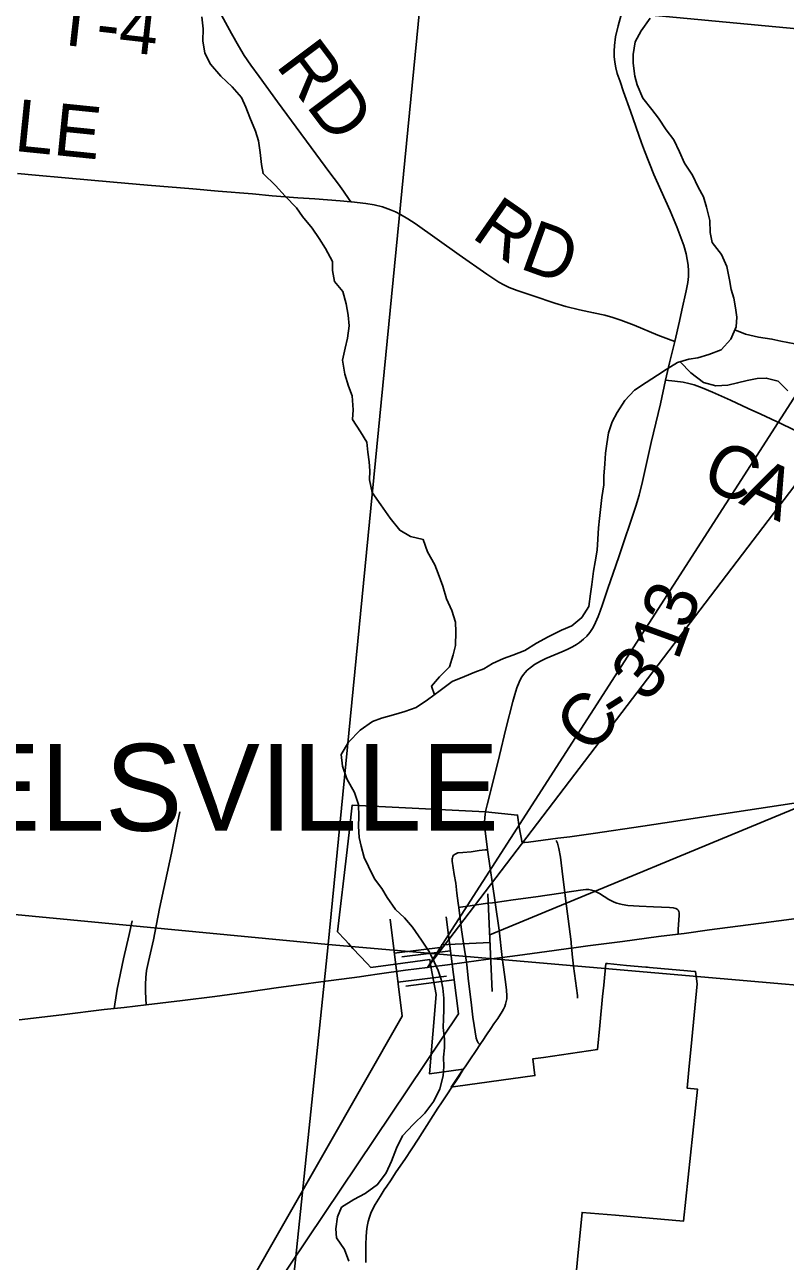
# Model space of a CAD drawing. Extents: x 0 to 1134, y 0 to 440.
# Drawn here: x 330.48 to 355.34, y 212.12 to 252.54 of the extents above; entities that cross this region are included whole.
import ezdxf

# ---------------------------------------------------------------- set-up
doc = ezdxf.new("R2010")
doc.units = 0
for name, color, linetype in [('GM_X_City_Street', 7, 'Continuous'), ('GM_X_Corporation', 7, 'Continuous'), ('GM_X_Corporation_Text', 7, 'Continuous'), ('GM_X_County_Road', 7, 'Continuous'), ('GM_X_County_Road_Text', 7, 'Continuous'), ('GM_X_Minor_River', 7, 'Continuous'), ('GM_X_Section', 7, 'Continuous'), ('GM_X_Township_Road', 7, 'Continuous'), ('GM_X_Township_Road_Text', 7, 'Continuous'), ('GM_X_US_Route', 7, 'Continuous'), ('SH_Data', 7, 'Continuous'), ('SH_Text', 7, 'Continuous'), ('SN_P_Signs', 7, 'Continuous')]:
    doc.layers.add(name, color=color, linetype=linetype)

msp = doc.modelspace()

# ---------------------------------------------------------------- linework, layer by layer
at = {"layer": 'GM_X_City_Street'}
for points in [[(344.92, 221.895), (344.858, 222.313), (344.813, 222.593), (344.761, 222.956), (344.671, 223.688), (344.654, 223.824), (344.606, 224.149), (344.567, 224.477), (344.523, 224.766), (344.456, 225.201), (344.453, 225.273), (344.459, 225.313), (344.469, 225.348), (344.488, 225.381), (344.514, 225.407), (344.55, 225.432), (344.594, 225.452), (344.639, 225.466), (344.801, 225.487), (345.076, 225.507), (345.337, 225.547), (345.529, 225.565), (345.609, 225.573)], [(348.358, 222.357), (348.338, 222.564), (348.306, 222.809), (348.157, 223.978), (348.134, 224.174), (348.072, 224.689), (347.99, 225.331), (347.941, 225.609), (347.891, 225.789), (347.855, 225.872)], [(345.855, 223.85), (346.448, 223.934), (347.186, 224.037), (348.007, 224.155), (348.134, 224.174), (348.645, 224.25), (348.828, 224.271), (348.921, 224.27), (349.012, 224.256), (349.1, 224.229), (349.185, 224.191), (349.268, 224.147), (349.423, 224.046), (349.578, 223.942), (349.66, 223.898), (349.745, 223.86), (349.832, 223.827), (349.921, 223.801), (350.011, 223.78), (350.195, 223.754), (350.567, 223.731), (351.031, 223.705), (351.554, 223.684), (351.679, 223.678), (351.769, 223.657), (351.814, 223.633), (351.842, 223.601), (351.86, 223.553), (351.87, 223.514), (351.873, 223.43), (351.84, 222.969), (351.842, 222.856), (351.843, 222.814)], [(344.671, 223.688), (344.727, 223.696), (344.963, 223.729), (345.545, 223.812), (345.768, 223.839), (345.855, 223.85)], [(348.554, 220.725), (348.546, 220.812), (348.423, 221.762), (348.377, 222.158), (348.363, 222.305), (348.358, 222.357)], [(345.357, 219.194), (345.341, 219.214), (345.305, 219.26), (345.268, 219.327), (345.241, 219.41), (345.204, 219.626), (345.17, 219.831), (345.133, 220.099), (345.072, 220.594), (344.99, 221.279), (344.93, 221.806), (344.92, 221.895)]]:
    msp.add_lwpolyline(points, dxfattribs=at)
at = {"layer": 'GM_X_Corporation'}
msp.add_lwpolyline([(348.202, 208.427), (348.555, 212.174), (348.701, 213.717), (349.796, 213.624), (352.021, 213.436), (352.475, 217.745), (352.137, 217.774), (352.194, 218.381), (352.287, 219.37), (352.458, 221.187), (352.412, 221.588), (352.373, 221.592), (352.022, 221.624), (351.645, 221.658), (350.909, 221.725), (350.841, 221.731), (350.786, 221.736), (350.156, 221.793), (349.533, 221.85), (349.481, 221.854), (349.406, 221.149), (349.365, 220.772), (349.277, 219.83), (349.202, 219.043), (347.436, 218.785), (347.085, 218.734), (347.157, 218.189), (344.566, 217.834), (344.416, 217.814), (344.809, 218.402), (343.716, 218.243), (343.926, 220.836), (343.76, 221.76), (343.72, 221.985), (342.365, 221.802), (341.789, 221.724), (341.671, 221.851), (341.209, 222.349), (341.061, 222.509), (340.949, 222.63), (340.704, 222.894), (341.016, 225.565), (341.094, 226.237), (341.188, 227.034), (345.537, 226.811), (346.592, 226.703), (346.638, 226.312), (346.738, 225.793), (346.82, 225.804), (346.951, 225.821), (347.902, 225.946), (348.304, 225.998), (349.064, 226.098), (350.685, 226.343), (351.401, 226.451), (353.04, 226.699), (356.276, 227.188)], dxfattribs=at)
at = {"layer": 'GM_X_County_Road'}
msp.add_line((345.855, 223.85), (345.609, 225.573), dxfattribs=at)
for points in [[(351.728, 242.189), (351.886, 242.846), (351.96, 243.204), (352.102, 243.841), (352.156, 244.118), (352.174, 244.305), (352.176, 244.494), (352.164, 244.682), (352.137, 244.868), (352.099, 245.052), (352.023, 245.323), (351.933, 245.589), (351.798, 245.937), (351.579, 246.453), (351.27, 247.131), (351.049, 247.642), (350.744, 248.42), (350.642, 248.679), (350.283, 249.71), (350.056, 250.341), (349.942, 250.682), (349.852, 250.946), (349.8, 251.133), (349.769, 251.315), (349.749, 251.5), (349.746, 251.676), (349.758, 251.863), (349.795, 252.142), (349.876, 252.501), (349.973, 252.86)], [(330.241, 247.679), (330.83, 247.623), (331.798, 247.531), (333.376, 247.388), (334.491, 247.299), (335.971, 247.173), (336.806, 247.099), (337.92, 247.007), (338.569, 246.951), (339.406, 246.885), (339.963, 246.845), (340.795, 246.78), (341.136, 246.749)], [(341.136, 246.749), (341.166, 246.746), (341.628, 246.694), (341.902, 246.649), (342.171, 246.583), (342.433, 246.493), (342.603, 246.42), (342.767, 246.337), (343.006, 246.195), (343.239, 246.042), (344.684, 245.018), (345.587, 244.38), (345.976, 244.124), (346.141, 244.033), (346.312, 243.954), (346.575, 243.855), (347.103, 243.672), (347.809, 243.435), (348.167, 243.328), (348.62, 243.217), (349.078, 243.123), (349.44, 243.043), (349.707, 242.97), (349.969, 242.88), (350.402, 242.714), (351.178, 242.397), (351.526, 242.265), (351.728, 242.189)], [(351.43, 240.926), (351.558, 241.483), (351.728, 242.189)], [(345.544, 226.799), (345.554, 226.864), (345.592, 227.043), (345.799, 227.852), (345.998, 228.651), (346.212, 229.52), (346.433, 230.418), (346.497, 230.648), (346.57, 230.869), (346.639, 231.048), (346.687, 231.143), (346.733, 231.22), (346.784, 231.299), (346.844, 231.371), (346.91, 231.44), (347.041, 231.553), (347.144, 231.624), (347.339, 231.734), (347.517, 231.824), (348.037, 232.041), (348.209, 232.12), (348.385, 232.203), (348.519, 232.278), (348.616, 232.347), (348.746, 232.45), (348.856, 232.557), (348.952, 232.67), (349.059, 232.832), (349.142, 233.004), (349.223, 233.201), (349.286, 233.372), (349.369, 233.592), (349.441, 233.815), (349.541, 234.115), (349.714, 234.608), (349.899, 235.144), (350.077, 235.668), (350.285, 236.278), (350.46, 236.806), (350.565, 237.16), (350.677, 237.611), (350.964, 238.881), (351.259, 240.149), (351.43, 240.926)], [(351.43, 240.926), (351.731, 240.892), (352.005, 240.853), (352.185, 240.813), (352.362, 240.764), (352.622, 240.674), (352.961, 240.532), (353.552, 240.266), (354.127, 240), (354.544, 239.806), (355.215, 239.49), (356.209, 239.013)], [(345.609, 225.573), (345.57, 225.847), (345.526, 226.184), (345.514, 226.359), (345.513, 226.487), (345.522, 226.611), (345.534, 226.734), (345.544, 226.799)], [(346.087, 222.054), (345.985, 222.94), (345.855, 223.85)], [(345.357, 219.194), (345.379, 219.228), (345.454, 219.341), (345.575, 219.518), (345.718, 219.731), (345.818, 219.878), (345.942, 220.059), (346.085, 220.282), (346.131, 220.362), (346.169, 220.444), (346.201, 220.527), (346.223, 220.614), (346.236, 220.703), (346.241, 220.794), (346.232, 220.979), (346.198, 221.256), (346.123, 221.814), (346.087, 222.054)], [(344.9, 218.51), (345.034, 218.709), (345.237, 219.011), (345.357, 219.194)], [(344.104, 217.3), (344.339, 217.657), (344.378, 217.716), (344.668, 218.155), (344.816, 218.386), (344.9, 218.51)], [(343.338, 216.112), (343.475, 216.32), (343.986, 217.121), (344.104, 217.3)], [(341.634, 212.083), (341.625, 212.332), (341.627, 212.69), (341.636, 212.907), (341.651, 213.099), (341.672, 213.261), (341.704, 213.423), (341.745, 213.563), (341.798, 213.698), (341.86, 213.83), (341.939, 213.977), (342.096, 214.241), (342.23, 214.452), (342.313, 214.575), (342.433, 214.752), (342.625, 215.044), (342.902, 215.451), (343.134, 215.8), (343.338, 216.112)]]:
    msp.add_lwpolyline(points, dxfattribs=at)
at = {"layer": 'GM_X_Minor_River'}
for points in [[(343.875, 230.64), (343.778, 230.922), (344.033, 231.226), (344.367, 231.553), (344.486, 231.939), (344.558, 232.246), (344.575, 232.69), (344.557, 233.009), (344.447, 233.387), (344.27, 233.776), (344.15, 234.188), (343.995, 234.6), (343.885, 234.886), (343.651, 235.311), (343.508, 235.711), (343.087, 235.807), (342.737, 236.017), (342.423, 236.408), (342.12, 236.845), (341.84, 237.247), (341.754, 237.658), (341.758, 237.954), (341.739, 238.251), (341.698, 238.571), (341.667, 238.89), (341.455, 239.235), (341.198, 239.637), (341.213, 239.955), (341.185, 240.412), (341.064, 240.721), (340.943, 241.121), (340.869, 241.578), (340.954, 241.965), (341.026, 242.294), (341.088, 242.693), (341.047, 243.046), (340.984, 243.412), (340.875, 243.824), (340.605, 244.146), (340.541, 244.5), (340.545, 244.796), (340.311, 245.221), (340.099, 245.554), (339.875, 245.887), (339.561, 246.267), (339.359, 246.555), (338.988, 246.935), (338.673, 247.281), (338.268, 247.673), (338.215, 247.97), (338.174, 248.358), (338.122, 248.747), (338.023, 249.056), (337.835, 249.502), (337.703, 249.846), (337.57, 250.155), (337.255, 250.513), (336.884, 250.859), (336.547, 251.251), (336.369, 251.606), (336.306, 252.017), (336.311, 252.405), (336.27, 252.793)], [(350.687, 250.136), (350.498, 250.572), (350.422, 250.857), (350.371, 251.28), (350.374, 251.565), (350.436, 251.974), (350.635, 252.337), (350.925, 252.755)], [(344.163, 219.762), (344.167, 220.047), (344.182, 220.343), (344.175, 220.719), (344.145, 221.05), (344.092, 221.335), (343.993, 221.621), (343.86, 221.908), (343.715, 222.228), (343.447, 222.619), (343.156, 223.044), (342.897, 223.343), (342.604, 223.62), (342.324, 224.011), (342.157, 224.309), (341.91, 224.62), (341.722, 225.021), (341.577, 225.319), (341.479, 225.685), (341.414, 225.97), (341.385, 226.347), (341.4, 226.654), (341.394, 227.053), (341.262, 227.442), (341.005, 227.889), (340.862, 228.301), (340.822, 228.689), (341.066, 229.085), (341.447, 229.479), (341.849, 229.76), (342.147, 229.87), (342.536, 229.979), (342.902, 230.089), (343.28, 230.221), (343.647, 230.467), (344.061, 230.782), (344.453, 231.073), (344.854, 231.239), (345.197, 231.372), (345.483, 231.483), (345.771, 231.662), (346.126, 231.828), (346.435, 231.927), (346.824, 232.082), (347.215, 232.328), (347.593, 232.529), (348.029, 232.751), (348.362, 232.896), (348.695, 233.165), (348.917, 233.527), (348.979, 233.937), (349.017, 234.244), (349.068, 234.676), (349.128, 234.983), (349.19, 235.359), (349.218, 235.723), (349.234, 236.099), (349.272, 236.395), (349.311, 236.793), (349.349, 237.089), (349.411, 237.499), (349.414, 237.784), (349.442, 238.182), (349.469, 238.535), (349.507, 238.842), (349.569, 239.195), (349.687, 239.558), (349.851, 239.864), (350.095, 240.26), (350.418, 240.598), (350.798, 240.844), (351.165, 241.079), (351.452, 241.27), (351.82, 241.493), (352.186, 241.603), (352.483, 241.656), (352.849, 241.755), (353.25, 241.909), (353.562, 242.259), (353.738, 242.667), (353.765, 242.975), (353.711, 243.283), (353.658, 243.603), (353.571, 243.889), (353.518, 244.197), (353.432, 244.631), (353.255, 245.033), (352.952, 245.424), (352.888, 245.744), (352.881, 246.143), (352.773, 246.577), (352.674, 246.909), (352.496, 247.23), (352.307, 247.62), (352.05, 248.011), (351.884, 248.389), (351.695, 248.779), (351.449, 249.101), (351.203, 249.48), (350.978, 249.768), (350.687, 250.136)], [(353.695, 242.569), (354.043, 242.424), (354.463, 242.328), (354.907, 242.266), (355.202, 242.194), (355.657, 242.109)], [(351.912, 241.521), (352.26, 241.158), (352.667, 240.845), (353.075, 240.737), (353.463, 240.756), (353.783, 240.832), (354.092, 240.908), (354.423, 240.972), (354.72, 240.991), (355.106, 240.884), (355.432, 240.572)], [(341.071, 212.12), (340.928, 212.51), (340.67, 212.889), (340.651, 213.185), (340.702, 213.572), (340.831, 213.889), (341.233, 214.135), (341.611, 214.335), (342.014, 214.627), (342.292, 215.011), (342.468, 215.396), (342.633, 215.816), (342.832, 216.223), (343.178, 216.595), (343.559, 216.967), (343.848, 217.351), (344.047, 217.758), (344.155, 218.179), (344.182, 218.486), (344.174, 218.794), (344.201, 219.101), (344.204, 219.386), (344.163, 219.762)]]:
    msp.add_lwpolyline(points, dxfattribs=at)
at = {"layer": 'GM_X_Section'}
for points in [[(346.29, 283.052), (376.424, 280.529), (373.702, 250.716), (343.437, 253.571)], [(313.682, 256.326), (343.437, 253.571), (340.398, 222.479), (310.554, 225.328)], [(343.437, 253.571), (373.702, 250.716), (370.553, 219.864), (340.398, 222.479)], [(310.554, 225.328), (340.398, 222.479), (337.3, 192.616), (307.774, 195.516)], [(340.398, 222.479), (370.553, 219.864), (367.659, 189.293), (337.3, 192.616)]]:
    msp.add_lwpolyline(points, close=True, dxfattribs=at)
at = {"layer": 'GM_X_Township_Road'}
for points in [[(341.136, 246.749), (341.084, 246.824), (340.896, 247.099), (340.732, 247.325), (340.452, 247.695), (338.741, 250.017), (338.137, 250.844), (337.865, 251.222), (337.655, 251.529), (337.463, 251.847), (337.234, 252.252), (336.576, 253.483)], [(334.446, 220.5), (334.426, 220.931), (334.423, 221.166), (334.435, 221.4), (334.458, 221.62), (334.521, 221.917), (334.687, 222.625), (334.882, 223.65), (335.274, 225.461), (335.477, 226.449), (335.548, 226.809)], [(333.407, 220.383), (333.425, 220.524), (333.452, 220.733), (333.503, 221.013), (333.709, 222.003), (333.887, 222.805), (333.991, 223.25)]]:
    msp.add_lwpolyline(points, dxfattribs=at)
at = {"layer": 'GM_X_US_Route'}
for points in [[(351.843, 222.814), (352.033, 222.838), (352.865, 222.951), (353.788, 223.077), (354.553, 223.169), (355.709, 223.32), (356.666, 223.453), (357.332, 223.542), (357.398, 223.551), (357.862, 223.613)], [(346.087, 222.054), (346.584, 222.121), (347.783, 222.281), (348.334, 222.354), (348.358, 222.357), (348.888, 222.428), (350.02, 222.574), (351.201, 222.733), (351.843, 222.814)], [(343.646, 221.728), (343.767, 221.744), (344.301, 221.812), (344.92, 221.895), (345.553, 221.98), (346.087, 222.054)], [(341.628, 221.449), (342.074, 221.513), (342.924, 221.631), (343.646, 221.728)], [(330.298, 220.01), (331.687, 220.175), (333.075, 220.349), (333.407, 220.383), (333.725, 220.415), (334.446, 220.5), (335.639, 220.647), (336.688, 220.78), (337.723, 220.919), (338.771, 221.068), (339.513, 221.165), (340.164, 221.251), (341.421, 221.419), (341.628, 221.449)]]:
    msp.add_lwpolyline(points, dxfattribs=at)
at = {"layer": 'SH_Data'}
for p, q in [((345.682, 222.786), (358.359, 228.041)), ((344.661, 220.205), (332.509, 202.117)), ((342.822, 220.128), (332.509, 202.117))]:
    msp.add_line(p, q, dxfattribs=at)
at = {"layer": 'SH_Text'}
msp.add_lwpolyline([(343.646, 221.728), (368.576, 260.481), (396.248, 260.648), (396.155, 254.95), (369.025, 255.034)], close=True, dxfattribs=at)
at = {"layer": 'SN_P_Signs'}
for p, q in [((345.762, 220.938), (345.623, 224.135)), ((342.822, 220.128), (342.42, 223.303)), ((344.661, 220.205), (344.259, 223.379)), ((342.561, 222.192), (344.148, 222.392)), ((345.693, 222.537), (344.094, 222.467)), ((344.4, 222.268), (342.812, 222.067)), ((342.621, 221.715), (342.621, 221.715)), ((342.621, 221.715), (342.621, 221.715)), ((344.46, 221.792), (344.46, 221.792)), ((344.46, 221.792), (344.46, 221.792)), ((342.681, 221.239), (344.269, 221.44)), ((344.52, 221.316), (342.933, 221.115))]:
    msp.add_line(p, q, dxfattribs=at)

# ---------------------------------------------------------------- texts
at = {"layer": 'GM_X_Corporation_Text'}
msp.add_text('DONNELSVILLE', height=2.84091, rotation=0, dxfattribs=at).set_placement((317.268, 226.193))
at = {"layer": 'GM_X_County_Road_Text'}
for s, rotation, p in [('L', 354.194, (330.103, 248.418)), ('E', 354.196, (331.372, 248.289)), ('R', 325.1679, (345.041, 245.608)), ('D', 340.127, (346.613, 244.59)), ('C', 335.0305, (352.519, 237.505)), ('A', 335.2699, (353.795, 236.91)), ('3', 70.5976, (352.193, 232.72)), ('1', 70.0619, (351.829, 231.717)), ('3', 48.968, (350.794, 230.338)), ('C', 50.0765, (348.999, 228.63)), ('-', 32.2751, (349.792, 229.612))]:
    msp.add_text(s, height=1.705, rotation=rotation, dxfattribs=at).set_placement(p)
at = {"layer": 'GM_X_Township_Road_Text'}
for s, rotation, p in [('T-4', 353.559, (331.367, 251.92)), ('RD', 306.8728, (338.661, 251.211))]:
    msp.add_text(s, height=1.7045, rotation=rotation, dxfattribs=at).set_placement(p)

doc.saveas('drawing.dxf')
